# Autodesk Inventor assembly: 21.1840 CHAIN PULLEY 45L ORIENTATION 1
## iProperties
Created: 2007-05
Part Number: 21.1840 CHAIN PULLEY 45L ORIENTATION 1
Document SubType Name: Assembly
Designer: Andy Moles
Mass: 385.71 g
Surface Area: 715.119 cm^2
Volume: 129.427 cm^3
Density: 2.98013 g/cm^3
Author: Andy Moles
